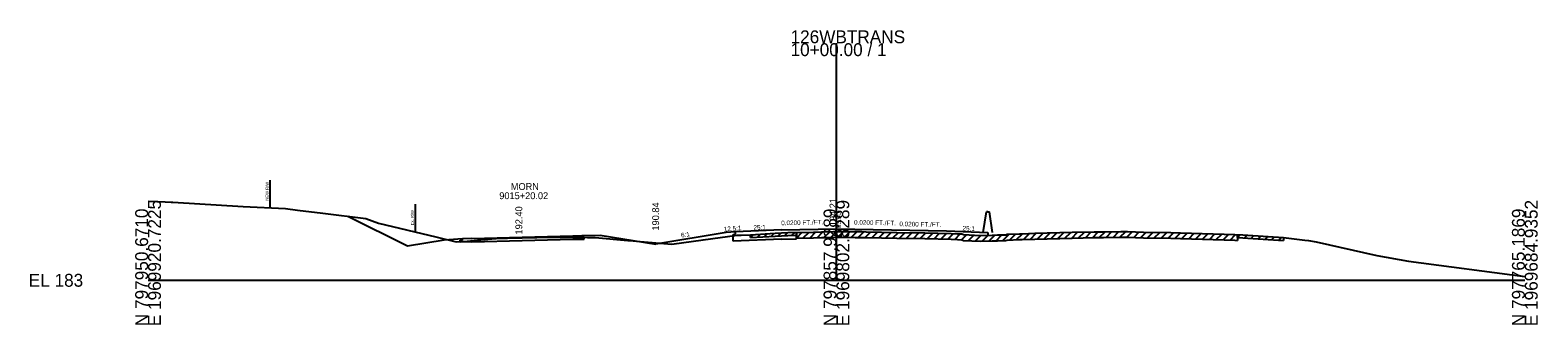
# Model space of a CAD drawing. Extents: x -6494 to 1970605, y -10 to 798140.
# Drawn here: x -25.7 to 302.8, y 2490.3 to 2554.4 of the extents above; entities that cross this region are included whole.
import ezdxf

# ---------------------------------------------------------------- set-up
doc = ezdxf.new("R2010")
doc.units = 0
for name, color, linetype in [('RD_GPK_XS_Cell', 7, 'Continuous'), ('RD_XS_Base', 7, 'Continuous'), ('RD_XS_EarthShd', 7, 'Continuous'), ('RD_XS_ExGround', 7, 'Continuous'), ('RD_XS_ExPaveRet', 7, 'Continuous'), ('RD_XS_ExRW', 7, 'Continuous'), ('RD_XS_MedBWall', 7, 'Continuous'), ('RD_XS_Misc_Line', 7, 'Continuous'), ('RD_XS_NewRW', 7, 'Continuous'), ('RD_XS_Pave', 7, 'Continuous'), ('RD_XS_PaveOvlay', 7, 'Continuous'), ('RD_XS_PaveShd', 7, 'Continuous'), ('RD_XS_TieSlope', 7, 'Continuous'), ('RD_XS_TX_Elev_EX', 7, 'Continuous'), ('RD_XS_TX_Elev_PR', 7, 'Continuous'), ('RD_XS_TX_Misc', 7, 'Continuous'), ('RD_XS_TX_Profile', 7, 'Continuous'), ('RD_XS_TX_ShdSlope', 7, 'Continuous'), ('RD_XS_TX_Slope', 7, 'Continuous'), ('RD_XS_TX_Station', 7, 'Continuous')]:
    doc.layers.add(name, color=color, linetype=linetype)

msp = doc.modelspace()

# ---------------------------------------------------------------- linework, layer by layer
at = {"layer": 'RD_GPK_XS_Cell'}
for p, q in [((150, 2500), (150, 2551.58)), ((0, 2500), (150, 2500)), ((150, 2500), (300, 2500))]:
    msp.add_line(p, q, dxfattribs=at)
at = {"layer": 'RD_XS_Base'}
for p, q in [((127.5, 2509.99), (128, 2510.01)), ((128, 2510.01), (128, 2510.57)), ((68.04, 2508.74), (68.54, 2508.75)), ((68.04, 2508.26), (68.04, 2508.74)), ((70.54, 2508.33), (68.04, 2508.26)), ((68.54, 2508.75), (68.54, 2509.05)), ((92.54, 2508.91), (95.04, 2508.98)), ((94.54, 2509.44), (94.54, 2509.74)), ((95.04, 2509.46), (94.54, 2509.44)), ((95.04, 2508.98), (95.04, 2509.46)), ((127.5, 2508.51), (127.5, 2509.99)), ((138, 2508.93), (127.5, 2508.51)), ((138, 2508.93), (141.27, 2508.99))]:
    msp.add_line(p, q, dxfattribs=at)
at = {"layer": 'RD_XS_EarthShd'}
for p, q in [((128, 2510.57), (126, 2510.41)), ((68.54, 2509.05), (64.54, 2508.73)), ((94.54, 2509.74), (98.54, 2509.85))]:
    msp.add_line(p, q, dxfattribs=at)
at = {"layer": 'RD_XS_ExGround'}
msp.add_lwpolyline([(0, 2517.19), (3.75, 2517.05), (5.03, 2517), (5.37, 2516.98), (20.75, 2516.06), (29.97, 2515.59), (32.59, 2515.29), (38.1, 2514.61), (47.44, 2513.41), (50.24, 2512.43), (62.69, 2509.45), (67.12, 2508.33), (69.56, 2508.5), (74.06, 2508.91), (76.69, 2509.16), (78.32, 2509.19), (87.92, 2509.38), (94.55, 2509.35), (95.79, 2509.34), (97.4, 2509.33), (104.57, 2508.66), (104.89, 2508.63), (107.26, 2508.43), (114.1, 2507.85), (120.96, 2508.79), (128.4, 2509.8), (129.25, 2509.84), (131.27, 2509.92), (136.62, 2510.23), (139.43, 2510.39), (145, 2510.5), (146.71, 2510.54), (149.36, 2510.59), (150, 2510.6), (151.31, 2510.63), (154.06, 2510.59), (155.51, 2510.58), (156.51, 2510.56), (163.15, 2510.43), (169.26, 2510.31), (175.03, 2510.19), (176.41, 2510.12), (177.36, 2510.07), (177.66, 2509.94), (181.3, 2509.75), (183.93, 2509.83), (185.06, 2509.86), (186.92, 2509.91), (187.17, 2510.01), (189.87, 2510.11), (190.46, 2510.14), (193.26, 2510.22), (201.4, 2510.44), (206.19, 2510.53), (208.19, 2510.56), (211.98, 2510.61), (213.1, 2510.63), (213.41, 2510.62), (216.93, 2510.49), (222.84, 2510.38), (224.95, 2510.34), (234.52, 2510.04), (236.8, 2509.97), (238.53, 2509.86), (247.4, 2509.31), (252.05, 2508.76), (252.89, 2508.66), (254.5, 2508.34), (267.77, 2505.42), (274.64, 2504.16), (300, 2500.84)], dxfattribs=at)
at = {"layer": 'RD_XS_ExPaveRet'}
for p, q in [((141.27, 2509.18), (141.27, 2510.43)), ((141.27, 2510.43), (141.27, 2509.8)), ((131.27, 2509.29), (131.27, 2509.92)), ((131.27, 2509.29), (136.62, 2509.6)), ((136.62, 2509.6), (139.43, 2509.76)), ((139.43, 2509.76), (141.27, 2509.8)), ((141.27, 2509.18), (145, 2509.25)), ((145, 2509.25), (146.71, 2509.29)), ((146.71, 2509.29), (149.36, 2509.34)), ((149.36, 2509.34), (150, 2509.35)), ((150, 2509.35), (151.31, 2509.38)), ((151.31, 2509.38), (154.06, 2509.34)), ((154.06, 2509.34), (155.51, 2509.33)), ((155.51, 2509.33), (156.51, 2509.31)), ((156.51, 2509.31), (163.15, 2509.18)), ((163.15, 2509.18), (169.26, 2509.06)), ((169.26, 2509.06), (175.03, 2508.94)), ((175.03, 2508.94), (176.41, 2508.87)), ((176.41, 2508.87), (177.36, 2508.82)), ((177.36, 2508.82), (177.66, 2508.69)), ((177.66, 2508.69), (181.3, 2508.5)), ((181.3, 2508.5), (183.93, 2508.58)), ((183.93, 2508.58), (185.06, 2508.61)), ((185.06, 2508.61), (186.92, 2508.66)), ((186.92, 2508.66), (187.17, 2508.76)), ((187.17, 2508.76), (189.87, 2508.86)), ((189.87, 2508.86), (190.46, 2508.89)), ((190.46, 2508.89), (193.26, 2508.97)), ((193.26, 2508.97), (201.4, 2509.19)), ((201.4, 2509.19), (206.19, 2509.28)), ((206.19, 2509.28), (208.19, 2509.31)), ((208.19, 2509.31), (211.98, 2509.36)), ((211.98, 2509.36), (213.1, 2509.38)), ((213.1, 2509.38), (213.41, 2509.37)), ((213.41, 2509.37), (216.93, 2509.24)), ((216.93, 2509.24), (222.84, 2509.13)), ((222.84, 2509.13), (224.95, 2509.09)), ((224.95, 2509.09), (234.52, 2508.79)), ((234.52, 2508.79), (236.8, 2508.72)), ((236.8, 2508.72), (237.39, 2508.68)), ((237.39, 2509.93), (237.39, 2508.68)), ((237.39, 2509.31), (237.39, 2509.93)), ((237.39, 2509.31), (238.53, 2509.24)), ((238.53, 2509.24), (247.4, 2508.69)), ((247.4, 2509.31), (247.4, 2508.69))]:
    msp.add_line(p, q, dxfattribs=at)
at = {"layer": 'RD_XS_ExRW'}
msp.add_line((58.17, 2516.59), (58.17, 2510.59), dxfattribs=at)
at = {"layer": 'RD_XS_MedBWall'}
for p, q in [((182, 2510.41), (182.67, 2514.89)), ((183, 2514.89), (182.67, 2514.89)), ((183, 2514.89), (183.33, 2514.89)), ((184, 2510.41), (183.33, 2514.89))]:
    msp.add_line(p, q, dxfattribs=at)
at = {"layer": 'RD_XS_Misc_Line'}
for p, q in [((132.77, 2509.38), (133.43, 2510.04)), ((134.27, 2509.47), (134.93, 2510.13)), ((135.77, 2509.55), (136.43, 2510.22)), ((137.27, 2509.64), (137.93, 2510.3)), ((138.77, 2509.73), (139.43, 2510.39)), ((140.27, 2509.78), (140.9, 2510.42)), ((141.27, 2509.18), (142.54, 2510.45)), ((142.77, 2509.21), (144.04, 2510.48)), ((144.27, 2509.24), (145.54, 2510.51)), ((145.77, 2509.27), (147.04, 2510.54)), ((147.27, 2509.3), (148.54, 2510.57)), ((148.77, 2509.33), (150.04, 2510.6)), ((150.27, 2509.36), (151.54, 2510.63)), ((151.77, 2509.38), (153, 2510.61)), ((153.27, 2509.36), (154.5, 2510.59)), ((154.77, 2509.34), (156, 2510.57)), ((156.27, 2509.31), (157.49, 2510.54)), ((157.77, 2509.28), (158.99, 2510.51)), ((159.27, 2509.26), (160.49, 2510.48)), ((160.77, 2509.23), (161.99, 2510.45)), ((162.27, 2509.2), (163.49, 2510.43)), ((163.77, 2509.17), (164.99, 2510.4)), ((165.27, 2509.14), (166.49, 2510.36)), ((166.77, 2509.11), (167.99, 2510.33)), ((168.27, 2509.08), (169.49, 2510.3)), ((169.77, 2509.05), (170.99, 2510.27)), ((171.27, 2509.01), (172.49, 2510.24)), ((172.77, 2508.98), (173.99, 2510.21)), ((174.27, 2508.95), (175.48, 2510.16)), ((175.77, 2508.9), (176.96, 2510.09)), ((186.27, 2508.64), (187.66, 2510.03)), ((187.77, 2508.78), (189.07, 2510.08)), ((189.27, 2508.84), (190.57, 2510.14)), ((190.77, 2508.89), (192.05, 2510.18)), ((192.27, 2508.94), (193.55, 2510.22)), ((193.77, 2508.98), (195.05, 2510.26)), ((195.27, 2509.02), (196.55, 2510.31)), ((196.77, 2509.06), (198.05, 2510.35)), ((198.27, 2509.1), (199.55, 2510.39)), ((199.77, 2509.15), (201.05, 2510.43)), ((201.27, 2509.19), (202.54, 2510.46)), ((202.77, 2509.21), (204.04, 2510.49)), ((204.27, 2509.24), (205.54, 2510.51)), ((205.77, 2509.27), (207.04, 2510.54)), ((207.27, 2509.29), (208.54, 2510.56)), ((208.77, 2509.31), (210.04, 2510.58)), ((210.27, 2509.34), (211.54, 2510.61)), ((211.77, 2509.36), (213.04, 2510.63)), ((213.27, 2509.37), (214.48, 2510.58)), ((214.77, 2509.32), (215.98, 2510.53)), ((216.27, 2509.27), (217.49, 2510.48)), ((217.77, 2509.23), (219, 2510.45)), ((219.27, 2509.2), (220.5, 2510.42)), ((220.77, 2509.17), (222, 2510.39)), ((222.27, 2509.14), (223.5, 2510.36)), ((223.77, 2509.11), (225, 2510.33)), ((225.27, 2509.08), (226.48, 2510.29)), ((226.77, 2509.03), (227.98, 2510.24)), ((228.27, 2508.98), (229.48, 2510.2)), ((229.77, 2508.94), (230.98, 2510.15)), ((231.27, 2508.89), (232.48, 2510.1)), ((232.77, 2508.84), (233.98, 2510.06)), ((234.27, 2508.8), (235.48, 2510.01)), ((131.27, 2509.29), (131.93, 2509.96)), ((177.27, 2508.82), (178.35, 2509.9)), ((178.77, 2508.63), (179.96, 2509.82)), ((180.27, 2508.56), (181.47, 2509.76)), ((181.77, 2508.52), (183.05, 2509.8)), ((183.27, 2508.56), (184.55, 2509.85)), ((184.77, 2508.6), (186.05, 2509.88)), ((235.77, 2508.75), (236.98, 2509.96)), ((237.39, 2509.31), (237.98, 2509.9)), ((238.89, 2509.22), (239.48, 2509.81)), ((240.39, 2509.12), (240.98, 2509.71)), ((241.89, 2509.03), (242.48, 2509.62)), ((243.39, 2508.94), (243.98, 2509.53)), ((244.89, 2508.84), (245.48, 2509.43)), ((246.39, 2508.75), (246.98, 2509.34))]:
    msp.add_line(p, q, dxfattribs=at)
at = {"layer": 'RD_XS_NewRW'}
msp.add_line((26.53, 2521.77), (26.53, 2515.77), dxfattribs=at)
at = {"layer": 'RD_XS_Pave'}
for p, q in [((138, 2510.97), (150, 2511.21)), ((150, 2511.21), (174, 2510.73)), ((70.54, 2509.11), (81.54, 2509.4)), ((70.54, 2508.33), (81.54, 2508.62)), ((81.54, 2509.4), (92.54, 2509.69)), ((81.54, 2508.62), (92.54, 2508.91))]:
    msp.add_line(p, q, dxfattribs=at)
at = {"layer": 'RD_XS_PaveOvlay'}
for p, q in [((141.27, 2510.43), (145, 2510.5)), ((141.27, 2510.43), (141.27, 2508.99)), ((145, 2510.5), (146.71, 2510.54)), ((146.71, 2510.54), (149.36, 2510.59)), ((149.36, 2510.59), (150, 2510.6)), ((150, 2510.6), (151.31, 2510.63)), ((151.31, 2510.63), (154.06, 2510.59)), ((154.06, 2510.59), (155.51, 2510.58)), ((155.51, 2510.58), (156.51, 2510.56)), ((156.51, 2510.56), (163.15, 2510.43)), ((163.15, 2510.43), (169.26, 2510.31)), ((169.26, 2510.31), (175.03, 2510.19)), ((175.03, 2510.19), (176.41, 2510.12)), ((176.41, 2510.12), (177.36, 2510.07)), ((177.36, 2510.07), (177.66, 2509.94)), ((177.66, 2509.94), (181.3, 2509.75)), ((181.3, 2509.75), (183.93, 2509.83)), ((183.93, 2509.83), (185.06, 2509.86))]:
    msp.add_line(p, q, dxfattribs=at)
at = {"layer": 'RD_XS_PaveShd'}
for p, q in [((138, 2510.97), (128, 2510.57)), ((174, 2510.73), (183, 2510.37)), ((183, 2510.37), (183, 2509.92)), ((70.54, 2509.11), (68.54, 2509.05)), ((92.54, 2509.69), (94.54, 2509.74))]:
    msp.add_line(p, q, dxfattribs=at)
at = {"layer": 'RD_XS_TieSlope'}
for p, q in [((56.54, 2507.4), (43.51, 2513.91)), ((126, 2510.41), (110.61, 2507.84)), ((64.54, 2508.73), (56.54, 2507.4)), ((98.54, 2509.85), (110.61, 2507.84)), ((110.61, 2507.84), (110.61, 2508.15))]:
    msp.add_line(p, q, dxfattribs=at)

# ---------------------------------------------------------------- texts
at = {"layer": 'RD_GPK_XS_Cell'}
for s, p in [('126WBTRANS', (140, 2551.58)), ('10+00.00 / 1', (140, 2548.78)), ('EL 183', (-26, 2498.6))]:
    msp.add_text(s, height=2.8, dxfattribs=at).set_placement(p)
for s, p in [('E 1969920.7225', (2.8, 2490)), ('E 1969802.8289', (152.8, 2490)), ('E 1969684.9352', (302.8, 2490)), ('N 797950.6710', (0, 2490)), ('N 797857.9289', (150, 2490)), ('N 797765.1869', (300, 2490))]:
    msp.add_text(s, height=2.8, rotation=90, dxfattribs=at).set_placement(p)
at = {"layer": 'RD_XS_ExRW'}
msp.add_text('Ex. R/W ', height=0.65, rotation=90, dxfattribs=at).set_placement((57.92, 2511.98))
at = {"layer": 'RD_XS_NewRW'}
msp.add_text('NEW R/W ', height=0.65, rotation=90, dxfattribs=at).set_placement((26.26, 2517.33))
at = {"layer": 'RD_XS_TX_Elev_EX'}
msp.add_text('193.60', height=1, rotation=90, dxfattribs=at).set_placement((151, 2510.6))
at = {"layer": 'RD_XS_TX_Elev_PR'}
for s, p in [(' 194.21', (150, 2511.21)), (' 192.40', (81.54, 2509.4))]:
    msp.add_text(s, height=1.5, rotation=90, dxfattribs=at).set_placement(p)
at = {"layer": 'RD_XS_TX_Misc'}
msp.add_text('190.84', height=1.5, rotation=90, dxfattribs=at).set_placement((111.36, 2510.81))
at = {"layer": 'RD_XS_TX_Profile'}
for rotation, p in [(2.2906, (131.94, 2510.97)), (357.7094, (177.46, 2510.84))]:
    msp.add_text('25:1', height=1, rotation=rotation, dxfattribs=at).set_placement(p)
at = {"layer": 'RD_XS_TX_ShdSlope'}
msp.add_text('12.5:1', height=1, rotation=4.5739, dxfattribs=at).set_placement((125.5, 2510.62))
at = {"layer": 'RD_XS_TX_Slope'}
for s, rotation, p in [('6:1', 9.4623, (116.22, 2509.28)), ('0.0200 FT./FT.', 1.1458, (137.98, 2511.97)), ('0.0200 FT./FT.', 358.8542, (153.83, 2512.13)), ('0.0200 FT./FT.', 358.8542, (163.7, 2511.78))]:
    msp.add_text(s, height=1, rotation=rotation, dxfattribs=at).set_placement(p)
at = {"layer": 'RD_XS_TX_Station'}
for s, p in [('MORN', (79.04, 2519.65)), ('9015+20.02', (76.53, 2517.65))]:
    msp.add_text(s, height=1.5, dxfattribs=at).set_placement(p)

doc.saveas('drawing.dxf')
